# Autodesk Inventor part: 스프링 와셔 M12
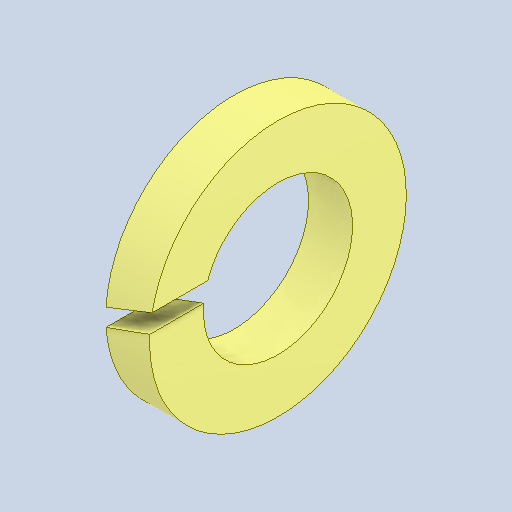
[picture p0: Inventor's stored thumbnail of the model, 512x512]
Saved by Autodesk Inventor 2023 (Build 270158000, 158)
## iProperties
Created: 2026-06
Part Number: 스프링 와셔 M12
Material: 강철, 연강
Description: 스프링 잠금 와셔
Document SubType Name: Modeling
Designer: home
Density: 7.85 g/cm^3
Appearance: 기본값
Author: jhkim
Sending System: Autodesk Inventor 2027
Preprocessor: ST-DEVELOPER v20.1
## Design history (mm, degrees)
feature "Solid1"
node "솔리드1"
